// Mitsubishi GX Works2 project: 带温度校准+PID温度控制+PID自动调谐整定   PLC: FX3U/FX3UC

PROGRAM MAIN
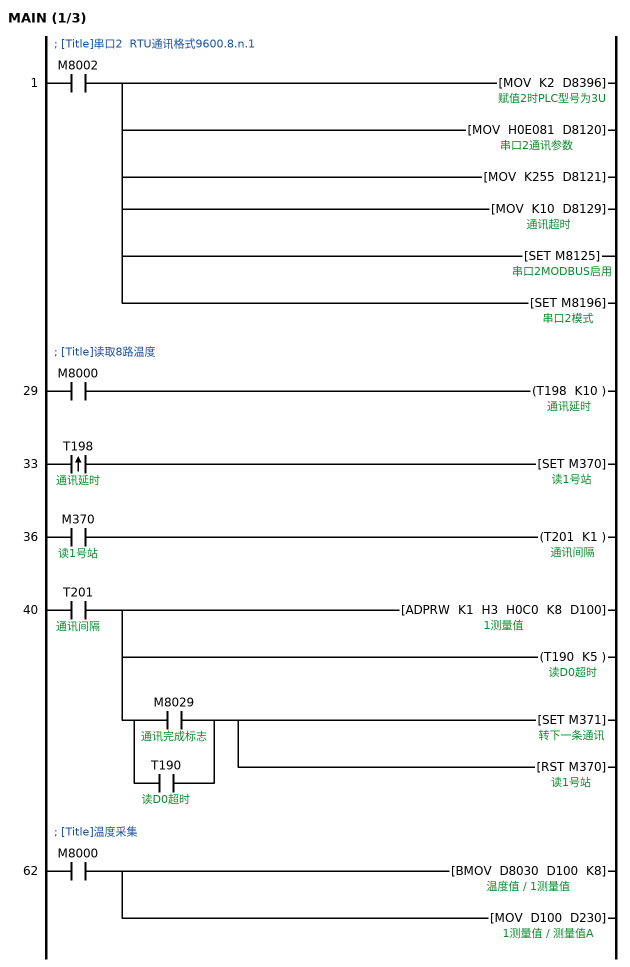
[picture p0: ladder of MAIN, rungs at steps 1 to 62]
; [Title]串口2  RTU通讯格式9600.8.n.1
1     LD      M8002
      MOV     K2 D8396  ; 赋值2时PLC型号为3U
      MOV     H0E081 D8120  ; 串口2通讯参数
        [note] 19200/8n1
      MOV     K255 D8121
        [note] 做主机D8121需设为最大255
      MOV     K10 D8129  ; 通讯超时
      SET     M8125  ; 串口2MODBUS启用
      SET     M8196  ; 串口2模式
; [Title]读取8路温度
29    LD      M8000
      OUT     T198 K10  ; 通讯延时
33    LDP     T198  ; 通讯延时
      SET     M370  ; 读1号站
36    LD      M370  ; 读1号站
      OUT     T201 K1  ; 通讯间隔
40    LD      T201  ; 通讯间隔
      ADPRW   K1 H3 H0C0 K8 D100  ; 1测量值
        [note] 用03号功能码读从站1的地址c0数据
      OUT     T190 K5  ; 读D0超时
      LD      M8029  ; 通讯完成标志
      OR      T190  ; 读D0超时
      ANB
      SET     M371  ; 转下一条通讯
      RST     M370  ; 读1号站
; [Title]温度采集
62    LD      M8000
      BMOV    D8030 D100 K8  ; 温度值
      MOV     D100 D230  ; 测量值A
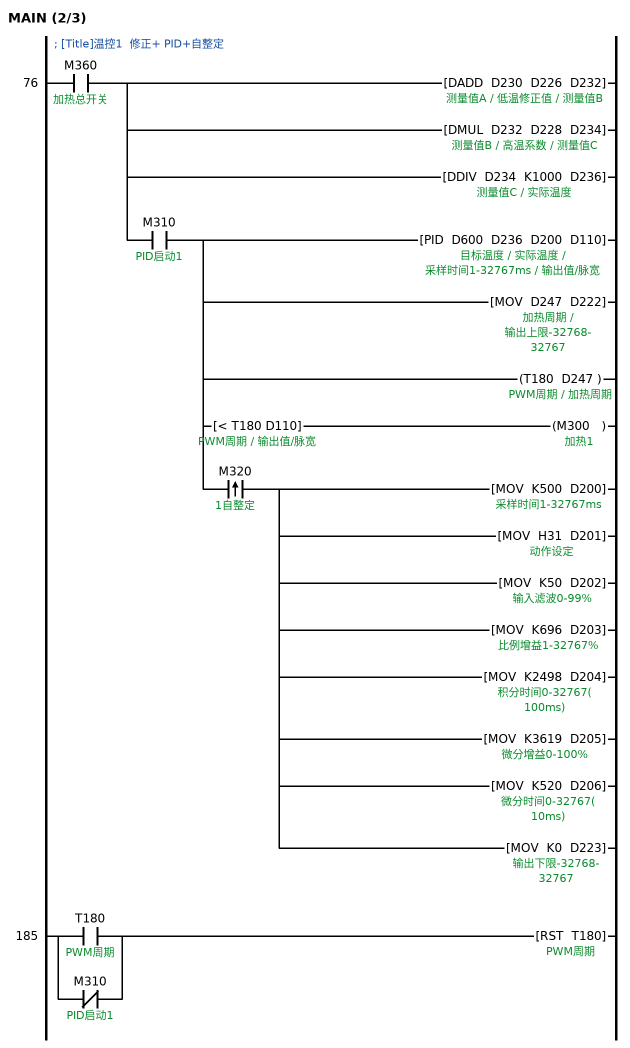
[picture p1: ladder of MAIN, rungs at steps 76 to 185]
; [Title]温控1  修正+ PID+自整定
76    LD      M360  ; 加热总开关
      DADD    D230 D226 D232  ; 低温修正值 / 测量值B
      DMUL    D232 D228 D234  ; 高温系数 / 测量值C
      DDIV    D234 K1000 D236  ; 实际温度
      AND     M310  ; PID启动1
      PID     D600 D236 D200 D110  ; 目标温度 / 采样时间1-32767ms / 输出值/脉宽
      MOV     D247 D222  ; 加热周期 / 输出上限-32768-32767
      OUT     T180 D247  ; PWM周期 / 加热周期
      MPS
      AND<    T180 D110  ; PWM周期 / 输出值/脉宽
      OUT     M300  ; 加热1
        [note] 加热器输出
      MPP
      ANDP    M320  ; 1自整定
      MOV     K500 D200
      MOV     H31 D201  ; 动作设定
      MOV     K50 D202  ; 输入滤波0-99%
      MOV     K696 D203  ; 比例增益1-32767%
      MOV     K2498 D204  ; 积分时间0-32767(100ms)
      MOV     K3619 D205  ; 微分增益0-100%
      MOV     K520 D206  ; 微分时间0-32767(10ms)
      MOV     K0 D223  ; 输出下限-32768-32767
185   LD      T180  ; PWM周期
      ORI     M310  ; PID启动1
      RST     T180  ; PWM周期
        [note] 加热器动作周期
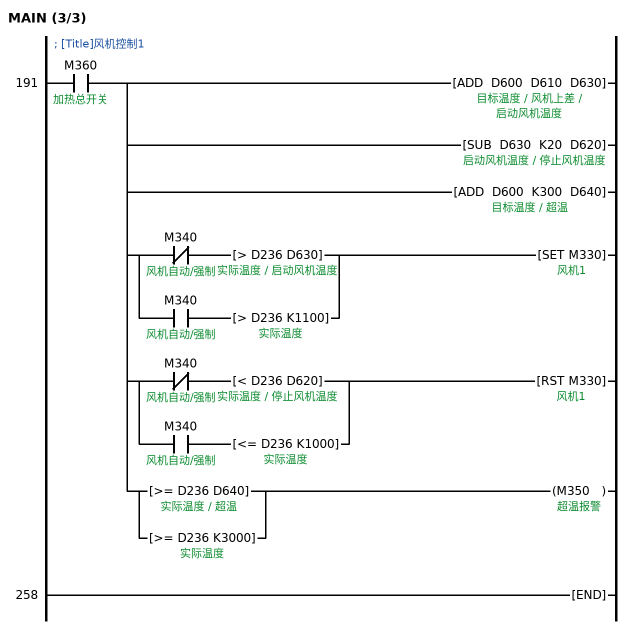
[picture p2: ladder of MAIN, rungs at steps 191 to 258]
; [Title]风机控制1
191   LD      M360  ; 加热总开关
      ADD     D600 D610 D630  ; 风机上差 / 启动风机温度
      SUB     D630 K20 D620  ; 停止风机温度
      ADD     D600 K300 D640  ; 超温
      MPS
      LDI     M340  ; 风机自动/强制
      AND>    D236 D630  ; 实际温度 / 启动风机温度
      LD      M340  ; 风机自动/强制
      AND>    D236 K1100  ; 实际温度
      ORB
      ANB
      SET     M330  ; 风机1
      MRD
      LDI     M340  ; 风机自动/强制
      AND<    D236 D620  ; 实际温度 / 停止风机温度
      LD      M340  ; 风机自动/强制
      AND<=   D236 K1000  ; 实际温度
      ORB
      ANB
      RST     M330  ; 风机1
      MPP
      LD>=    D236 D640  ; 实际温度 / 超温
      OR>=    D236 K3000  ; 实际温度
      ANB
      OUT     M350  ; 超温报警
258   END
END_PROGRAM

// device comments not shown above
X000  ; 急停
Y010  ; 挤出启动
Y014  ; 真空启动
Y015  ; 加热1
Y016  ; 加热2
Y017  ; 加热3
Y020  ; 加热4
Y021  ; 加热5
Y022  ; 风机1
Y023  ; 风机2
Y024  ; 风机3
Y025  ; 风机4
Y026  ; 风机5
